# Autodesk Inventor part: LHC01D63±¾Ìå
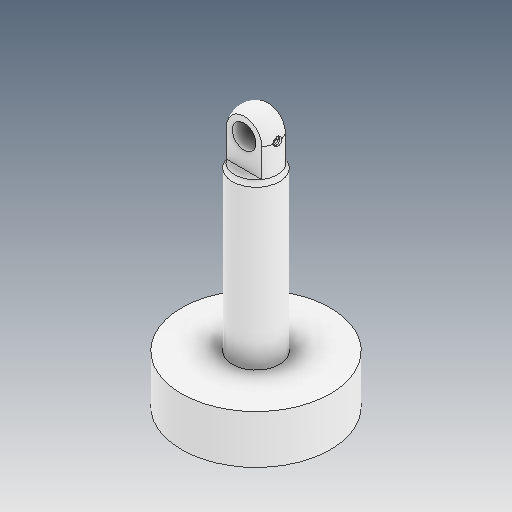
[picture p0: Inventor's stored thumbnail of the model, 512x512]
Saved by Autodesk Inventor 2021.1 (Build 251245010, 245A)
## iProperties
Created: 2021-06
Part Number: LHC01D63±¾Ìå
Material: Ogólny
Document SubType Name: Modeling
Designer: user
Density: 1 g/cm^3
Appearance: Domyślna
Author: user
Revision Number: ÈÎºÎ
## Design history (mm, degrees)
feature "ÊäÈë1"
node "Bryła1"
